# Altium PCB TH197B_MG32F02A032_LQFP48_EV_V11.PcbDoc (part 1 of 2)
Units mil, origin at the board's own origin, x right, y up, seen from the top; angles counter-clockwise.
Board outline 4094.49 x 2637.8 mil, 2 copper layers (Top Layer, Bottom Layer); 114 components, 111 nets, 502 pads, 245 vias.
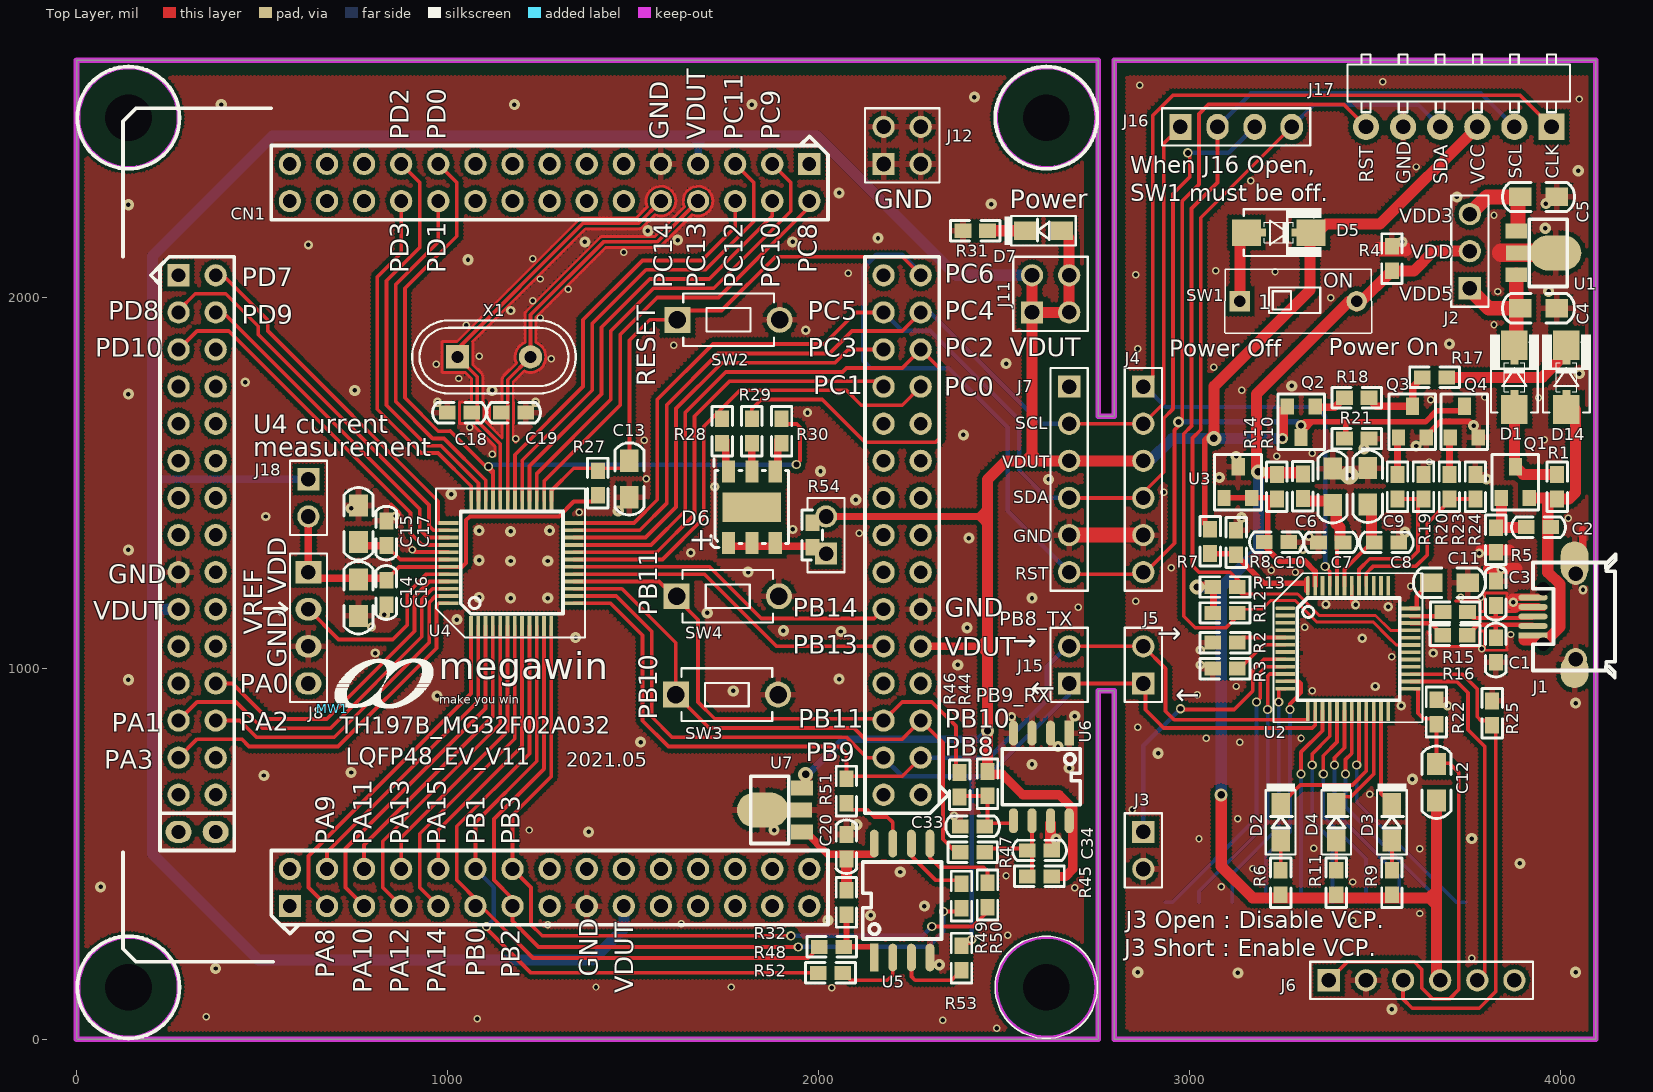
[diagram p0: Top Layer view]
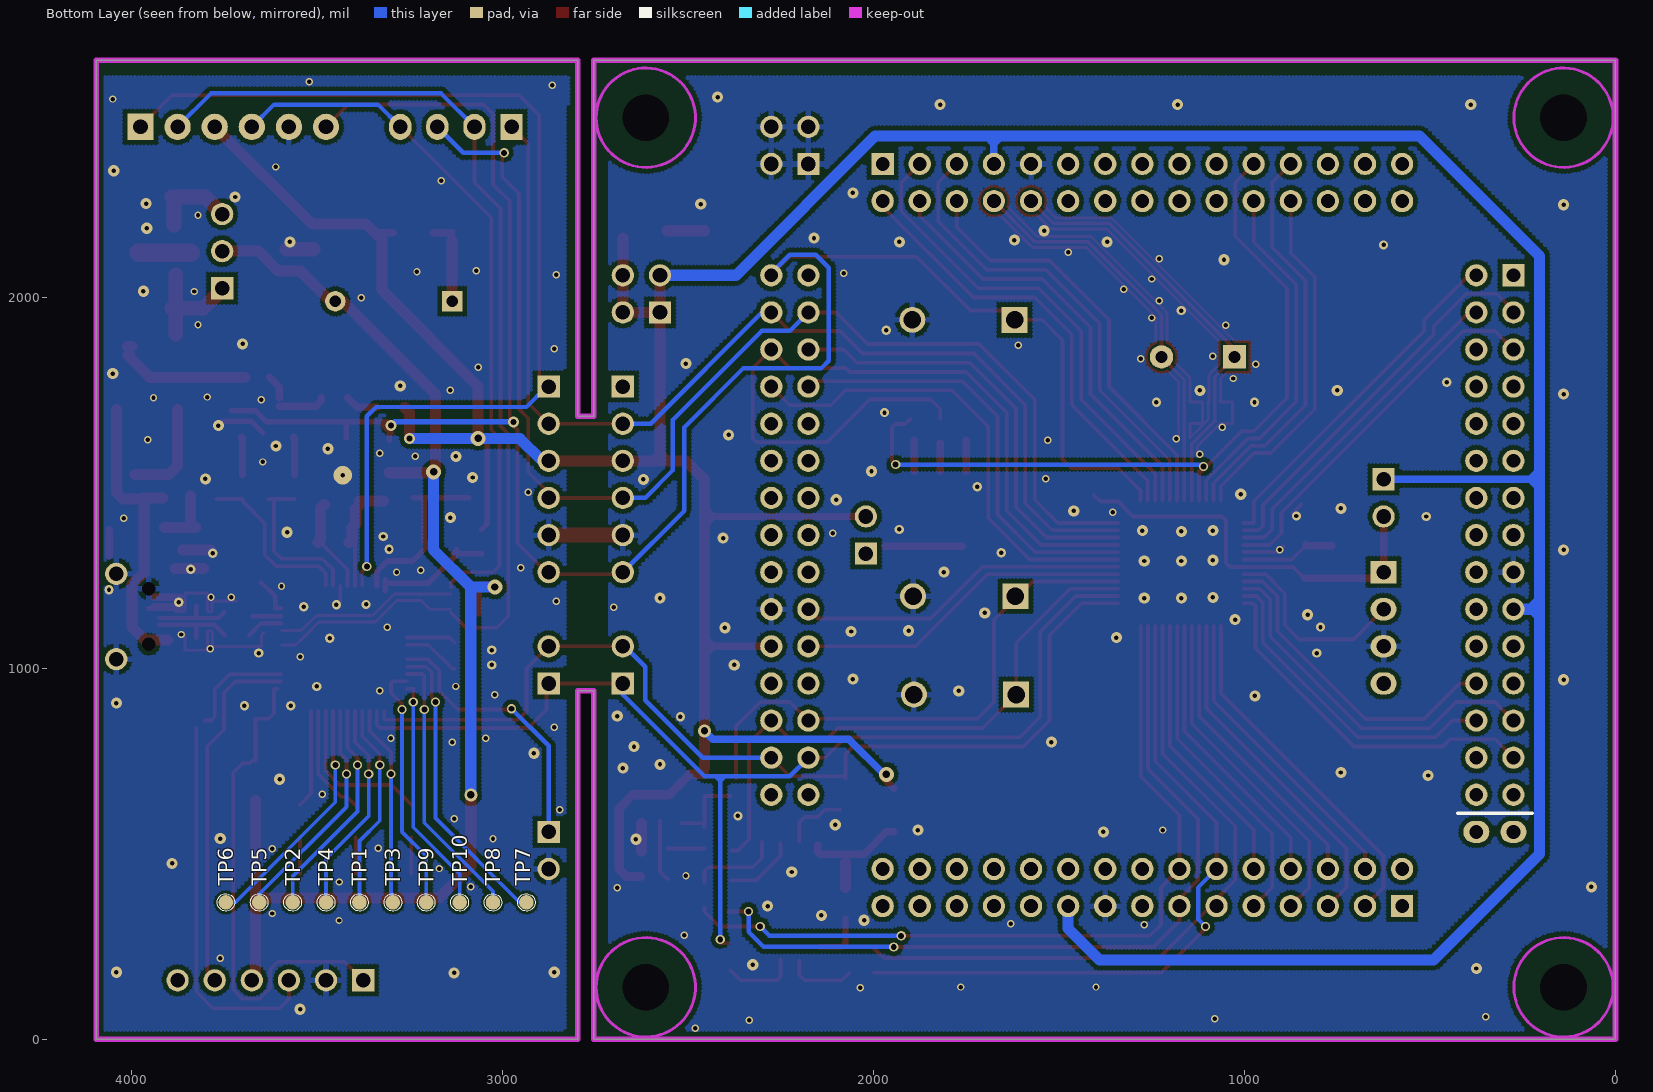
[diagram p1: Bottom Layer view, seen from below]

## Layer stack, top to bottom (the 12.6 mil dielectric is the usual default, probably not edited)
Top Layer: signal copper 1.4
Dielectric: dielectric 12.6, FR-4, Dk 4.8
Bottom Layer: signal copper 1.4

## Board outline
0,0 0,2637.8 2753.39,2637.8 2753.39,1678.74 2796.69,1678.74 2796.69,2637.8 4094.49,2637.8 4094.49,0 2796.69,0 2796.69,938.74 2753.39,938.74 2753.39,0

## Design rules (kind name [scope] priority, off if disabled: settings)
Clearance 12 [All] p1 off: gap=12
Clearance 7 [All] p2 off: gap=7
Clearance 6 [All] p3: gap=6
HoleSize 500-HoleSize [All] p1: absolutevalues=TRUE maxlimit=1500 minlimit=1 maxpercent=80.000 minpercent=20.000
PolygonConnect VIA [ISVIA] p1: connectstyle=Direct reliefconductorwidth=10 reliefentries=4 polygonreliefangle="90 Angle"
PolygonConnect "15 PolygonConnect" [All] p2: connectstyle=Relief reliefconductorwidth=15 reliefentries=4 polygonreliefangle="90 Angle"
RoomDefinition 2_MG32F02A032_V11 [InComponentClass('2_MG32F02A032_V11')] p1: confinementstyle=ConfineIn formatcopy=TRUE lockcomponents=FALSE outline -190,-175 4240.04,-175 4240.04,2710 -190,2710
RoomDefinition 1_MLink_V11 [InComponentClass('1_MLink_V11')] p2: confinementstyle=ConfineIn formatcopy=TRUE lockcomponents=FALSE outline -110,-220 4180,-220 4180,2775 -110,2775
RoutingVias [All] p1: holewidth=16 width=28 viastyle="Through Hole" minholewidth=16 minwidth=25 maxholewidth=28 maxwidth=50
ShortCircuit [All] p1 off: allowed=FALSE
SilkscreenOverComponentPads [All] p1: minsilkscreentomaskgap=10
SolderMaskExpansion [All] p1: expansion=4
UnRoutedNet [All] p1 off:
Width [All] p1: maxlimit=100 minlimit=6 preferedwidth=10
24 further rules are at their usual default settings.

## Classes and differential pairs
component class 1_MLink_V11: C1 C2 C3 C4 C5 C6 C7 C8 C9 C10 C11 C12 D1 D2 D3 D4 D5 D14 J1 J2 J3 J4 J5 J6 J16 J17 MW1 Q1 Q2 Q3 Q4 R1 R2 R3 R4 R5 R6 R7 R8 R9 R10 R11 R12 R13 R14 R15 R16 R17 R18 R19 R20 R21 R22 R23 R24 R25 SW1 TP1 TP2 TP3 TP4 TP5 TP6 TP7 TP8 TP9 TP10 U1 U2 U3
component class 2_MG32F02A032_V11: C13 C14 C15 C16 C17 C18 C19 C20 C33 C34 CN1 D6 D7 J7 J8 J11 J12 J15 J18 R27 R28 R29 R30 R31 R32 R44 R45 R46 R47 R48 R49 R50 R51 R52 R53 R54 SW2 SW3 SW4 U4 U5 U6 U7 X1

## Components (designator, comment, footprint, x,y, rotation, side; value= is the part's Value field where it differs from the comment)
C1 "15pF" 0603C 3825.04,1048.74 r90 top
C2 "0.1uF" 0603C 3940,1380 r0 top
C3 "15pF" 0603C 3825.04,1201.74 r270 top
C4 "4.7uF" 0805C 3940,1970 r0 top
C5 "4.7uF" 0805C 3940,2270 r0 top
C6 "4.7uF" 0805C 3385,1488.74 r90 top
C7 "0.1uF" 0603C 3380.04,1338.74 r180 top
C8 "0.1uF" 0603C 3530.04,1338.74 r0 top
C9 "4.7uF" 0805C 3480,1490 r90 top
C10 "0.1uF" 0603C 3234.09,1339.69 r180 top
C11 "4.7uF" 0805C 3700,1230 r0 top
C12 "4.7uF" 0805C 3665.04,692.74 r90 top
C13 "4.7uF" 0805C 1490,1510 r90 top
C14 "4.7uF" 0805C 760,1190 r270 top
C15 "4.7uF" 0805C 760,1389.21 r90 top
C16 "0.1uF" 0603C 834.94,1203.74 r90 top
C17 "0.1uF" 0603C 835,1363.74 r270 top
C18 "NC" 0603C 1032.04,1688.74 r0 top
C19 "NC" 0603C 1178.04,1688.74 r180 top
C20 "1uF" 0603C 2075.04,518.74 r270 top
C33 "47pF" 0603C 2415.04,573.74 r0 top
C34 "47pF" 0603C 2595.04,508.74 r180 top
CN1 "QFP122-CKT" QFP122-P2.54-CKT 1275.04,1358.74 r0 top locked
D1 "1N5817" DIODE_SMA_SOD323 3875,1783.74 r90 top
D2 "Yellow" 0805D 3245.04,585 r90 top
D3 "Green" 0805D 3545.04,585 r90 top
D4 "Red" 0805D 3395.04,585 r90 top
D5 "1N5817" DIODE_SMA_SOD323 3240,2173.74 r0 top
D6 "GTG5050RGBC" LED6P_RGB_SMD_50X50 1820.04,1433.74 r90 top
D7 "Yellow" 0805D 2605.83,2178.74 r180 top
D14 "1N5817" DIODE_SMA_SOD323 4015,1783.74 r90 top
J1 "Micro USB" JACK_USB_SMD290X220P065 3925.04,1139.21 r180 top (schematic designator J8)
J2 "2&3 (0 ohm)" PS3P254 3755.04,2023.74 r90 top
J3 "VCP Option" PS2P254 2875.04,558.74 r270 top
J4 "OnBoard ICP/SWD Connector" PS6P254 2875.04,1758.74 r270 top
J5 "NC" PS2P254 2875.04,958.74 r90 top
J6 "CON6" PS6P254 3375.04,158.74 r0 top
J7 "CON6" PS6P254 2675.04,1758.74 r270 top
J8 "1&2 (0 ohm)" PS4P254 625.04,1258.74 r270 top
J11 "CONN SOCKET 2x2/SM" PS2X2P254 2575.04,1958.74 r0 top
J12 "CONN SOCKET 2x2/SM" PS2X2P254 2175.04,2358.74 r0 top
J15 "NC" PS2P254 2675.04,958.74 r90 top
J16 "When J16 Open, SW1 must be off." PS4P254 2975.04,2458.74 r0 top
J17 "Off Board ICP/SWD Connector" PS6P254_90 3975.04,2458.74 r180 top locked
J18 "JUMPER" PS2P254 625.04,1508.74 r270 top
MW1 "MW-A4" MEGAWIN_3.4 690,890 r0 top
Q1 "IRLML6402" SOT23 3877.54,1500.71 r0 top
Q2 "2N3906" SOT23 3300.5,1663.74 r180 top
Q3 "3904" SOT23_132 3600.04,1663.74 r0 top
Q4 "3904" SOT23_132 3740.04,1663.74 r0 top
R1 "NC" 0603R#1 3990.04,1488.74 r270 top
R2 "0" 0603R#1 3095.04,1068.74 r0 top
R3 "NC" 0603R#1 3095.04,998.74 r0 top
R4 "3.3K" 0603R#1 3545.04,2103.74 r270 top
R5 "1M" 0603R#1 3825.04,1345.74 r270 top
R6 "1K" 0603R#1 3245.04,422 r270 top
R7 "30K" 0603R#1 3055.04,1341.74 r90 top
R8 "10K" 0603R#1 3125.04,1338.74 r270 top
R9 "1K" 0603R#1 3545.04,422 r270 top
R10 "10" 0603R#1 3305,1490 r90 top
R11 "1K" 0603R#1 3395.04,422 r270 top
R12 "1.5K" 0603R#1 3095.04,1148.74 r180 top
R13 "1.5K" 0603R#1 3095.04,1218.74 r180 top
R14 "1K" 0603R#1 3235,1488.74 r270 top
R15 "30" 0603R#1 3715.88,1151.05 r180 top
R16 "30" 0603R#1 3715.04,1088.74 r180 top
R17 "4.7K" 0603R#1 3660,1783.74 r0 top
R18 "1K" 0603R#1 3450.04,1728.74 r0 top
R19 "4.7K" 0603R#1 3560.04,1488.74 r270 top
R20 "10K" 0603R#1 3630.04,1488.74 r270 top
R21 "1M" 0603R#1 3450.04,1618.74 r180 top
R22 "47K" 0603R#1 3665.04,881.74 r90 top
R23 "4.7K" 0603R#1 3700.04,1488.74 r270 top
R24 "10K" 0603R#1 3770.04,1488.74 r270 top
R25 "47K" 0603R#1 3815.04,878.74 r270 top
R27 "47K" 0603R#1 1405.04,1498.74 r270 top
R28 "510" 0603R#1 1740.04,1638.74 r90 top
R29 "510" 0603R#1 1820.04,1638.74 r90 top
R30 "3K" 0603R#1 1900.04,1638.74 r90 top
R31 "1K" 0603R#1 2422.04,2178.74 r180 top
R32 "47K" 0603R#1 2075.04,368.74 r270 top
R44 "10K" 0603R#1 2455.04,688.74 r90 top
R45 "10K" 0603R#1 2595.04,438.74 r0 top
R46 "NC" 0603R#2 2380,685.74 r270 top
R47 "NC" 0603R#1 2415.04,503.74 r180 top
R48 "NC" 0603R#1 2035.04,248.74 r180 top
R49 "NC" 0603R#1 2385.04,385.74 r270 top
R50 "NC" 0603R#1 2455.04,388.74 r270 top
R51 "NC" 0603R#1 2075.04,668.74 r90 top
R52 "NC" 0603R#1 2032.04,178.74 r180 top
R53 "NC" 0603R#1 2385.04,218.74 r90 top
R54 "0" PS2p254+0603 2020,1308.74 r90 top
SW1 "SW KEY-SPST" DIP2_SW 3135.08,1988.74 r0 top
SW2 "SW TACT-SPST" SW_T_2P 1757.24,1938.74 r0 top
SW3 "SW TACT-SPST" SW_T_2P 1752.83,928.74 r0 top
SW4 "SW TACT-SPST" SW_T_2P 1755.04,1193.74 r0 top
TP1 "T POINT A" PIN1_1H0 3385.04,368.74 r90 bottom
TP2 "T POINT A" PIN1_1H0 3565.04,368.74 r90 bottom
TP3 "T POINT A" PIN1_1H0 3295.04,368.74 r180 bottom
TP4 "T POINT A" PIN1_1H0 3475.04,368.74 r180 bottom
TP5 "T POINT A" PIN1_1H0 3655.04,368.74 r180 bottom
TP6 "T POINT A" PIN1_1H0 3745.04,368.74 r180 bottom
TP7 "T POINT A" PIN1_1H0 2935.04,368.74 r180 bottom
TP8 "T POINT A" PIN1_1H0 3025.04,368.74 r180 bottom
TP9 "T POINT A" PIN1_1H0 3205.04,368.74 r180 bottom
TP10 "T POINT A" PIN1_1H0 3115.04,368.74 r90 bottom
U1 "AIC1734-33(SOT-89)" SOT89 3880,2119.06 r270 top
U2 "MG84FG516_LQFP48" LQFP48_7X7_050#1 3426.51,1053.13 r270 top locked
U3 "TL431A" SOT23 3130,1500.71 r0 top
U4 "MG32F02A_LQFP48" LQFP48_7X7_050#2 1171.3,1282.7 r0 top locked
U5 "MX25LXX-SOP" SO8_208P127 2225.04,373.74 r0 top
U6 "24C16-SOP" SO8_150P127 2675.04,824.96 r270 top
U7 "AIC1734-33(SOT-89)" SOT89 1955.04,617.8 r90 top
X1 "NC" X49U 1125.04,1838.74 r0 top

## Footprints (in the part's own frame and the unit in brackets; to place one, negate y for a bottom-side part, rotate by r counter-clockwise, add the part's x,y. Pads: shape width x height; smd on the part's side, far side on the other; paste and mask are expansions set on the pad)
0603C [mil]
  rect 45x38 smd: 1(33,0) 2(-33,0)
  silkscreen extent -72,-28 72,28
0603R#1 [mil]
  rect 45x38 smd: 1(33,0) 2(-33,0)
  silkscreen extent -67,-28 67,28
0603R#2 [mil]
  rect 45x38 smd: 1(-33,0) 2(33,0)
  silkscreen extent -67,-28 67,28
0805C [mil]
  rect 60x50 smd: 1(-49.21,0) 2(49.21,0)
  silkscreen extent -97,-39 97,39
0805D [mil]
  rect 60x50 smd: 1(-49.21,0) 2(49.21,0)
  silkscreen extent -87,-40 104,40
DIODE_SMA_SOD323 [mm]
  rect 2x1.8 smd: 1(-2.2,0) 2(2.2,0)
  rect 0.95x0.54 smd: 1(-1.35,0) 2(1.35,0)
  silkscreen extent -2.4,-1.68 2.92,1.68
DIP2_SW [mm]
  rect 1.4x1.4 hole 0.8: 1(0,0)
  round 1.4 hole 0.8: 2(8,0)
  silkscreen extent -1.02,-2.2 9.02,2.2
JACK_USB_SMD290X220P065 [mm]
  rect 1.9x1.8 on Mech2: 0(-2.85,-1.15) 0(-2.85,1.15)
  round 0.8 hole 0.9 unplated: 1(-0.7,1.9) 5(-0.7,-1.9)
  rect 2x0.4 smd: 1(0,1.3)
  oval 2x0.4 smd: 2(0,0.65) 3(0,0) 4(0,-0.65) 5(0,-1.3)
  round 1.524 hole 1: 5(-2.931,2.921) 6(-2.931,-2.921)
  oval 1.9x2.3 smd: 5(-2.85,3.75)
  oval 1.9x2.794 smd: 6(-2.85,-3.75)
  silkscreen extent -5.65,-4.25 -0.01,4.2
LED6P_RGB_SMD_50X50 [mm]
  rect 2x4 smd: 0(0,0)
  rect 1.5x0.9 smd: 1(-2.45,1.6) 2(2.45,1.6) 3(-2.45,0) 4(2.45,0) 5(-2.45,-1.6) 6(2.45,-1.6)
  silkscreen extent -2.76,-2.52 3.3,2.79
LQFP48_7X7_050#1 [mm]
  oval 0.254x1.35 smd: 1(-2.75,-4.292)
  rect 0.254x1.35 smd: 2(-2.25,-4.292) 3(-1.75,-4.292) 4(-1.25,-4.292) 5(-0.75,-4.292) 6(-0.25,-4.292) 7(0.25,-4.292) 8(0.75,-4.292) 9(1.25,-4.292) 10(1.75,-4.292) 11(2.25,-4.292) 12(2.75,-4.292) 25(2.763,4.292) 26(2.263,4.292) 27(1.763,4.292) 28(1.263,4.292) 29(0.763,4.292) 30(0.263,4.292) 31(-0.237,4.292) 32(-0.737,4.292) 33(-1.237,4.292) 34(-1.737,4.292) 35(-2.237,4.292) 36(-2.737,4.292)
  rect 1.35x0.254 smd: 13(4.286,-2.744) 14(4.286,-2.244) 15(4.286,-1.744) 16(4.286,-1.244) 17(4.286,-0.744) 18(4.286,-0.244) 19(4.286,0.256) 20(4.286,0.756) 21(4.286,1.256) 22(4.286,1.756) 23(4.286,2.256) 24(4.286,2.756) 37(-4.286,2.756) 38(-4.286,2.256) 39(-4.286,1.756) 40(-4.286,1.256) 41(-4.286,0.756) 42(-4.286,0.256) 43(-4.286,-0.244) 44(-4.286,-0.744) 45(-4.286,-1.244) 46(-4.286,-1.744) 47(-4.286,-2.244)
  oval 1.35x0.254 smd: 48(-4.286,-2.744)
  silkscreen extent -5.15,-5.09 5.05,5.11
LQFP48_7X7_050#2 [mm]
  rect 0.254x1.35 smd: 1(-2.75,-4.292) 2(-2.25,-4.292) 3(-1.75,-4.292) 4(-1.25,-4.292) 5(-0.75,-4.292) 6(-0.25,-4.292) 7(0.25,-4.292) 8(0.75,-4.292) 9(1.25,-4.292) 10(1.75,-4.292) 11(2.25,-4.292) 12(2.75,-4.292) 25(2.763,4.292) 26(2.263,4.292) 27(1.763,4.292) 28(1.263,4.292) 29(0.763,4.292) 30(0.263,4.292) 31(-0.237,4.292) 32(-0.737,4.292) 33(-1.237,4.292) 34(-1.737,4.292) 35(-2.237,4.292) 36(-2.737,4.292)
  rect 1.35x0.254 smd: 13(4.286,-2.744) 14(4.286,-2.244) 15(4.286,-1.744) 16(4.286,-1.244) 17(4.286,-0.744) 18(4.286,-0.244) 19(4.286,0.256) 20(4.286,0.756) 21(4.286,1.256) 22(4.286,1.756) 23(4.286,2.256) 24(4.286,2.756) 37(-4.286,2.756) 38(-4.286,2.256) 39(-4.286,1.756) 40(-4.286,1.256) 41(-4.286,0.756) 42(-4.286,0.256) 43(-4.286,-0.244) 44(-4.286,-0.744) 45(-4.286,-1.244) 46(-4.286,-1.744) 47(-4.286,-2.244) 48(-4.286,-2.744)
  silkscreen extent -5.15,-5.09 5.05,5.11
MEGAWIN_3.4 [mil]
  silkscreen extent 5,3 272,136
PIN1_1H0 [mm]
  round 1 smd: 1(0,0)
  silkscreen extent -0.6,-0.6 0.6,0.6
PS2P254 [mil]
  rect 60x60 hole 39.37: 1(0,0)
  round 60 hole 39.37: 2(100,0)
  silkscreen extent -50,-50 150,50
PS2p254+0603 [mil]
  rect 60x60 hole 39.37: 1(0,0)
  rect 45x38 smd: 1(17,36.85) 2(83,36.85)
  round 60 hole 39.37: 2(100,0)
  silkscreen extent -50,-50 150,64
PS2X2P254 [mil]
  rect 60x60 hole 39.37: 1(0,0)
  round 60 hole 39.37: 2(0,100) 3(100,0) 4(100,100)
  silkscreen extent -50,-50 150,150
PS3P254 [mil]
  rect 60x60 hole 39.37: 1(0,0)
  round 60 hole 39.37: 2(100,0) 3(200,0)
  silkscreen extent -50,-50 250,50
PS4P254 [mil]
  rect 60x70 hole 39.37: 1(0,0)
  oval 60x70 hole 39.37: 2(100,0) 3(200,0) 4(300,0)
  silkscreen extent -50,-50 350,50
PS6P254 [mil]
  rect 60x60 hole 39.37: 1(0,0)
  round 60 hole 39.37: 2(100,0) 3(200,0) 4(300,0) 5(400,0) 6(500,0)
  silkscreen extent -50,-50 550,50
PS6P254_90 [mm]
  rect 1.8x1.8 hole 1: 1(0,0)
  round 1.8 hole 1: 2(2.54,0) 3(5.08,0) 4(7.62,0) 5(10.16,0) 6(12.7,0)
  silkscreen extent -1.27,-4.95 13.97,-1
QFP122-P2.54-CKT [mil]
  rect 60x60 hole 37: 1(-700,-1000) 61(700,1000) 91(-1000,700)
  round 60 hole 37: 2(-700,-900) 3(-600,-1000) 4(-600,-900) 5(-500,-1000) 6(-500,-900) 7(-400,-1000) 8(-400,-900) 9(-300,-1000) 10(-300,-900) 11(-200,-1000) 12(-200,-900) 13(-100,-1000) 14(-100,-900) 15(0,-1000) 16(0,-900) 17(100,-1000) 18(100,-900) 19(200,-1000) 20(200,-900) 21(300,-1000) 22(300,-900) 23(400,-1000) 24(400,-900) 25(500,-1000) 26(500,-900) 27(600,-1000) 28(600,-900) 29(700,-1000) 30(700,-900) 31(1000,-700) 32(900,-700) 33(1000,-600) 34(900,-600) 35(1000,-500) 36(900,-500) 37(1000,-400) 38(900,-400) 39(1000,-300) 40(900,-300) 41(1000,-200) 42(900,-200) 43(1000,-100) 44(900,-100) 45(1000,0) 46(900,0) 47(1000,100) 48(900,100) 49(1000,200) 50(900,200) 51(1000,300) 52(900,300) 53(1000,400) 54(900,400) 55(1000,500) 56(900,500) 57(1000,600) 58(900,600) 59(1000,700) 60(900,700) 62(700,900) 63(600,1000) 64(600,900) 65(500,1000) 66(500,900) 67(400,1000) 68(400,900) 69(300,1000) 70(300,900) 71(200,1000) 72(200,900) 73(100,1000) 74(100,900) 75(0,1000) 76(0,900) 77(-100,1000) 78(-100,900) 79(-200,1000) 80(-200,900) 81(-300,1000) 82(-300,900) 83(-400,1000) 84(-400,900) 85(-500,1000) 86(-500,900) 87(-600,1000) 88(-600,900) 89(-700,1000) 90(-700,900) 92(-900,700) 93(-1000,600) 94(-900,600) 95(-1000,500) 96(-900,500) 97(-1000,400) 98(-900,400) 99(-1000,300) 100(-900,300) 101(-1000,200) 102(-900,200) 103(-1000,100) 104(-900,100) 105(-1000,0) 106(-900,0) 107(-1000,-100) 108(-900,-100) 109(-1000,-200) 110(-900,-200) 111(-1000,-300) 112(-900,-300) 113(-1000,-400) 114(-900,-400) 115(-1000,-500) 116(-900,-500) 117(-1000,-600) 118(-900,-600) 119(-1000,-700) 120(-900,-700)
  oval 70x60 hole 37: 121(-1000,-800) 122(-900,-800)
  silkscreen extent -1150,-1150 1075,1150
SO8_150P127 [mil]
  rect 67x25 smd: 1(0,0)
  oval 67x25 smd: 2(0,-50) 3(0,-100) 4(0,-150) 5(236.22,-150) 6(236.22,-100) 7(236.22,-50) 8(236.22,0)
  silkscreen extent 43,-180 193,30
SO8_208P127 [mm]
  rect 0.6x1.9 smd: 1(-1.905,-3.9)
  oval 0.6x1.9 smd: 2(-0.635,-3.9) 3(0.635,-3.9) 4(1.905,-3.9) 5(1.905,3.9) 6(0.635,3.9) 7(-0.635,3.9) 8(-1.905,3.9)
  silkscreen extent -2.69,-2.63 2.69,2.63
SOT23 [mil]
  rect 36x43.31 smd: 1(-37.5,-41.97) 2(37.5,-41.97)
  rect 36x46.06 smd: 3(0.5,41.97)
  silkscreen extent -63,-74 63,75
SOT23_132 [mil]
  rect 36x43.31 smd: 1(-37.5,-41.97) 3(37.5,-41.97)
  rect 36x46.06 smd: 2(0.5,41.97)
  silkscreen extent -63,-74 63,75
SOT89 [mm]
  rect 1.016x1.5 smd: 1(-1.5,0) 3(1.5,0)
  oval 2.4x3.5 smd: 2(0,2.7)
  rect 1.016x2.6 smd: 2(0,0.6)
  silkscreen extent -2.3,0.9 2.3,3.5
SW_T_2P [mil]
  rect 70x70 hole 47.24: 1(-137.79,0)
  round 70 hole 47.24: 2(137.8,0)
  silkscreen extent -122,-71 122,71
X49U [mm]
  rect 1.6x1.6 hole 0.8: 1(-2.5,0)
  round 1.6 hole 0.8: 2(2.5,0)
  silkscreen extent -5.6,-2.5 5.6,2.5

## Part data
C1 C3 C7 C12 C13 C14 C15 C16 C17: library part "CAP NP_Dup1"
C2 C8 C10: library part "CAP NP"
C4 C5: library part "C NP"
C6 C9 C11: library part CAP
C18 C19: library part "C NP_Dup1"
C20 C33 C34: library part CAP-NP
D1 D5 D14: library part "DIODE SCHOTTKY"
D2 D3 D4: library part Led0_0
D6: library part LED_GTG5050RGBC
D7: library part LED
J1 J7: library part CON6_Dup1
J2: library part CON3
J3 J5 J15: library part CON2
J4 J17: library part CON6
J8 J16: library part CON4
MW1: library part MW_A4_2
Q1: library part "MOSFET P GSD"
Q2: library part 2N3906_0
Q3 Q4: library part "NPN BCE"
R1 R2 R3 R4 R27: library part R_Dup4
R5 R6 R7 R8 R9 R11 R12 R13 R17 R18 R19 R22 R23 R25: library part R_Dup2
R10 R14 R15 R16 R28 R29 R30 R31 R32 R46 R47 R48 R49 R50 R51 R52 R53 R54: library part R_Dup5
R20 R21 R24: library part R_Dup1
R44 R45: library part R
U1 U7: library part AIC1722-33
U3: library part TL431/CYL
U4: library part IC-MG32F02A032-LQFP48
U5: library part ICM-25LXX
U6: library part ICM-24CXX
X1: library part CRYSTAL

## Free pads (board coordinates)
  round 120 hole 125.98 unplated: 0(140,140) 0(140,2483.43) 0(2613.39,140) 0(2613.39,2483.43)

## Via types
v1: diameter 30, hole 12, Top Layer to Bottom Layer, tented both sides, 93 vias
v2: diameter 20, hole 12, Top Layer to Bottom Layer, tented both sides, 89 vias
v3: diameter 25, hole 12, Top Layer to Bottom Layer, tented both sides, 32 vias
v4: diameter 25, hole 16, Top Layer to Bottom Layer, tented both sides, 21 vias
v5: diameter 40, hole 20, Top Layer to Bottom Layer, tented both sides, 4 vias
v6: diameter 30, hole 16, Top Layer to Bottom Layer, tented both sides, 3 vias
v7: diameter 35, hole 20, Top Layer to Bottom Layer, tented both sides, 2 vias
v8: diameter 50, hole 12, Top Layer to Bottom Layer, tented both sides, 1 vias

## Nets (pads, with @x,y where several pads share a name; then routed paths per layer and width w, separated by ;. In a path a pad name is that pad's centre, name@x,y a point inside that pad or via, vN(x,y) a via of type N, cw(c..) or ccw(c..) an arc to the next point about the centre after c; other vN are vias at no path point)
2.495V: C10.1 R14.1 U2.47 U3.1 U3.2 | length 478.9
  Top Layer w15: U3.1@3090,1458.74 U3.1@3092.5,1458.74 U3.2@3167.5,1458.74 3210,1458.74 3210,1455.74 C10.1@3210,1339.69 ; C10.1@3201.09,1339.69 3201.09,1328.91 3241.26,1288.74 3310.04,1288.74 3338.18,1260.6 U2.47@3338.18,1221.87 ; 3215,1458.74 3235,1458.74 R14.1@3240,1458.74
516P24: TP7.1 U2.9 | length 970.5
  Top Layer w10: v4(3180.04,908.74) 3190.04,918.74 3190.04,988.74 3205.22,1003.92 U2.9@3257.52,1003.92
  Bottom Layer w10: TP7.1@2935.04,368.74 2952.76,368.74 3180.04,596.02 ; 3066.4,482.38 3180.04,596.02 ; v4(3180.04,908.74) 3180.04,596.02
516P25: TP8.1 U2.10 | length 736.4
  Top Layer w10: v4(3210.04,888.74) 3210.04,978.74 3215.53,984.23 U2.10@3257.52,984.23
  Bottom Layer w10: TP8.1@3025.04,368.74 3025.04,398.59 3210.04,583.59 v4(3210.04,888.74)
516P26: TP9.1 U2.11 | length 674.3
  Top Layer w10: U2.11@3257.52,964.55 3294.23,964.55 3300.04,958.74 3300.04,933.74 3270.04,903.74 v4(3270.04,888.74)
  Bottom Layer w10: TP9.1@3205.04,368.74 3205.04,493.74 3270.04,558.74 v4(3270.04,888.74)
516P27: TP10.1 U2.12 | length 649.5
  Top Layer w10: v4(3240.04,908.74) 3240.04,941.97 3237.15,944.86 U2.12@3257.52,944.86
  Bottom Layer w10: TP10.1@3115.04,368.74 3115.04,446.17 3240.04,571.17 v4(3240.04,908.74)
516P32: TP3.1 U2.15 | length 762.5
  Top Layer w10: v4@3300.04,713.74 v4(3300.04,715) 3300.04,773.74 3357.86,831.56 U2.15@3357.86,884.39
  Bottom Layer w10: TP3.1@3300.04,373.74 3300.04,628.74 ; 3300.04,400.87 3300.04,628.74 ; v4@3300.04,713.74 3300.04,628.74
516P33: TP1.1 U2.16 | length 558.1
  Top Layer w10: v4(3330.04,738.74) 3330.04,768.74 3377.55,816.25 U2.16@3377.55,884.39
  Bottom Layer w10: v4(3330.04,738.74) 3330.04,588.89 3385.04,533.89 TP1.1@3385.04,368.74
516P34: TP4.1 U2.17 | length 578.7
  Top Layer w10: v4@3360.04,713.74 v4(3360.04,715) 3360.04,763.74 3397.23,800.93 U2.17@3397.23,884.39
  Bottom Layer w10: v4@3360.04,713.74 3360.04,601.31 3475.04,486.31 TP4.1@3475.04,368.74
516P35: TP2.1 U2.18 | length 599.3
  Top Layer w10: v4(3390.04,738.74) 3390.04,758.74 3416.92,785.62 U2.18@3416.92,884.39
  Bottom Layer w10: v4(3390.04,738.74) 3390.04,613.74 3565.04,438.74 TP2.1@3565.04,368.74
516P36: TP5.1 U2.19 | length 619.9
  Top Layer w10: v4@3420.04,713.74 v4(3420.04,715) 3420.04,753.74 3436.6,770.3 U2.19@3436.6,884.39
  Bottom Layer w10: v4@3420.04,713.74 3420.04,626.17 3655.04,391.17 TP5.1@3655.04,368.74
516P37: TP6.1 U2.20 | length 655.2
  Top Layer w10: v4(3450.04,738.74) 3456.29,744.99 U2.20@3456.29,884.39
  Bottom Layer w10: v4(3450.04,738.74) 3450.04,638.59 3719.89,368.74 TP6.1@3745.04,368.74
CHIP_VDD: C14.1 C16.1 J8.1 J18.2 R27.1 U4.43 | length 1144.1
  Top Layer w10: C16.1@835.04,1238.74 838.04,1241.74 C16.1@841.54,1245.24 ; 935.81,1273.11 U4.43@1002.56,1273.11
  Top Layer w11: C16.1@841.54,1245.24 869.41,1273.11 U4.43@1002.56,1273.11 1039.41,1273.11 1050.04,1283.74 1050.04,1398.74 1060.04,1408.74 1300.04,1408.74 1340.04,1448.74 1388.04,1448.74 R27.1@1405.04,1465.74
  Top Layer w20: J8.1@625.04,1258.74 J18.2@625.04,1408.74 ; J8.1@642.04,1241.74 760,1241.74 834.94,1241.74 C16.1@838.04,1241.74
D+: C3.1 J1.3 R15.2 | length 211.2
  Top Layer w12: R15.2@3748.88,1151.05 3764.71,1135.21 J1.3@3925.04,1135.21 ; 3825.04,1140.21 C3.1@3825.04,1168.74
D-: C1.1 J1.2 R16.2 | length 219.3
  Top Layer w12: R16.2@3748.04,1088.74 3776.51,1117.21 J1.2@3925.04,1117.21 ; C1.1@3825.04,1081.74 3825.04,1112.21
DET_VDUT: R7.2 R8.1 U2.48 | length 338.6
  Top Layer w15: R7.2@3055.04,1308.74 3125.04,1308.74 R8.1@3132.6,1308.74 ; R8.1@3122.6,1318.74 R8.1@3130.32,1311.02 ; R8.1@3122.8,1305.98 3124.04,1304.74 3200.04,1228.74 3310.98,1228.74 ; U2.48@3315.04,1208.74 3315.04,1221.87 U2.48@3315.04,1238.74
DUT_CLK: J4.1 J17.1 U2.45 | length 2858.5
  Top Layer w10: J4.1@2875.04,1758.74 2900.04,1783.74 2900.04,2488.74 2955.04,2543.74 3890.04,2543.74 J17.1@3975.04,2458.74 ; v4(3364.92,1273.74) 3377.55,1261.11 U2.45@3377.55,1221.87
  Bottom Layer w12: J4.1@2875.04,1758.74 2880.04,1758.74 2935.04,1703.74 3339.92,1703.74 3364.92,1678.74 v4(3364.92,1273.74)
DUT_RST: C13.2 CN1.59 J4.6 J7.6 J17.6 Q2.3 Q4.2 R21.1 R27.2 SW2.1 U4.25 | length 5757
  Top Layer w10: U4.25@1280.07,1451.69 1280.07,1478.77 1340.04,1538.74 1405.04,1538.74 1465.83,1538.74 1488.15,1561.06 1490.04,1562.95 1490.04,1883.74 1545.04,1938.74 SW2.1@1619.45,1938.74 ; SW2.1@1630.95,1963.74 1738.54,1963.74 1883.54,2108.74 2225.04,2108.74 CN1.59@2275.04,2058.74 ; J7.6@2676.04,1252.74 2875.04,1252.74 2878.04,1255.74 2958.79,1336.49 2958.79,1641.49 2975.54,1658.24 2980.04,1662.74 2980.04,1663.74 2980.04,2258.74 3025.04,2303.74 3025.04,2493.74 3050.04,2518.74 3415.04,2518.74 J17.6@3475.04,2458.74
  Top Layer w15: Q2.3@3300,1633.74 Q2.3@3305,1638.74 ; v6(3300,1653.74) 3310,1663.74 3330,1663.74 ; Q2.3@3305,1613.74 3305,1621.77 Q2.3@3305,1638.74 ; v6@3305,1656.74 3305,1653.74 Q2.3@3305,1638.74 ; R21.1@3420,1620.74 3420,1663.74 ; Q4.2@3730.63,1693.74 3665,1693.74 3635,1663.74 3420,1663.74 ; Q2.3@3305,1638.74 3310,1643.74 3330,1663.74 ; 3330,1663.74 3420,1663.74
  Bottom Layer w12: CN1.59@2275.04,2058.74 CN1.59@2280.04,2058.74 ; CN1.59@2295.04,2058.74 CN1.59@2280.04,2058.74 ; J7.6@2675.04,1258.74 2510.04,1423.74 2510.04,1648.74 2350.04,1808.74 2140.04,1808.74 2120.04,1828.74 2120.04,2078.74 2155.04,2113.74 2225.04,2113.74 2277.54,2061.24 CN1.59@2280.04,2058.74
  Bottom Layer w15: v6(2970.04,1663.74) 3290,1663.74 v6(3300,1653.74)
FAIL: D4.2 U2.22 | length 305.7
  Top Layer w10: D4.2@3395.04,629.74 3397.28,631.98 3419.04,653.74 3435.04,653.74 3495.66,714.36 U2.22@3495.66,884.39
FLASH_CEN: R32.1 R48.2 U5.1 | length 141.1
  Top Layer w15: R32.1@2075.04,325.74 2075.04,258.74 2076.54,257.24 2085.04,248.74 U5.1@2145.04,248.74
FLASH_D0: R50.2 U5.5 | length 245
  Top Layer w10: U5.5@2300.04,532.28 U5.5@2300.04,527.28 2300.04,488.74 2325.04,463.74 2445.04,463.74 2455.04,453.74 R50.2@2455.04,421.74
FLASH_D1: R52.2 U5.2 | length 188
  Top Layer w10: R52.2@2065.04,178.74 2085.04,158.74 2185.04,158.74 2200.04,173.74 U5.2@2200.04,212.2
FLASH_D2: R53.2 U5.3 | length 196.8
  Top Layer w10: U5.3@2250.04,215.2 2250.04,168.74 2260.04,158.74 2358.04,158.74 R53.2@2385.04,185.74
FLASH_D3: R51.2 U5.7 | length 176
  Top Layer w10: R51.2@2090.04,618.74 2130.04,618.74 2150.04,598.74 2185.04,598.74 2200.04,583.74 U5.7@2200.04,532.28
FLASH_SCK: R49.2 U5.6 | length 195.5
  Top Layer w10: U5.6@2250.04,527.28 2250.04,493.74 2315.04,428.74 R49.2@2385.04,428.74
GND_POWER: C1.2 C3.2 C4.2 C5.2 C6.2 C7.1 C8.1 C9.2 C10.2 C11.2 C13.1 C14.2 C15.2 C16.2 C17.2 C18.2 C19.2 C20.2 C33.2 C34.2 CN1.17 CN1.41 CN1.69 CN1.107 J1.4 J1.5 J1.6 J3.2 J4.5 J6.2 J7.5 J8.3 J12.1 J12.2 J12.3 J12.4 J17.5 Q3.3 Q4.3 R2.2 R3.2 R4.2 R5.1 R8.2 R20.2 R21.2 R22.1 R24.2 R25.2 R31.1 SW2.2 SW3.2 SW4.2 U1.2 U2.42 U3.3 U4.41 U5.4 U6.1 U6.2 U6.3 U6.4 U6.7 U7.2 | length 6567.9
  Top Layer w8: 1067.75,1880.24 1160.6,1973.08 1243.1,2055.58 1371.25,2183.74 1515.04,2183.74 ; 1068.11,1880.24 1068.11,1818.46 1090.64,1795.93 cw(c1080.04,1785.32) 1095.04,1785.32 ; 1069.44,1655.57 1127.27,1597.74 1127.27,1576.53 v2@1127.27,1571.74 ; 1090.65,1795.92 cw(c1080.04,1785.32) 1095.04,1785.32 ; 1095.04,1717.74 1095.04,1785.32 ; 1097.54,1717.74 1097.54,1669.89 1146.96,1620.48 1146.96,1659.74 1112.54,1659.74 1112.54,1717.74 1146.96,1717.74 1146.96,1777.23 ; 1176.96,1659.74 1176.96,1618.74 1176.96,1615.77 1178.97,1613.76 v2@1183.96,1608.77 ; 1176.96,1717.74 1176.96,1771.02 1206.71,1800.78 ccw(c1223.46,1838.74) 1264.96,1838.74 ccw(c1223.46,1838.74) 1238.46,1877.43 1238.46,1943.74 1238.46,1945.95 ; 1177.54,1659.74 1177.54,1717.74 ; 1212.85,1962.77 ccw(c1223.46,1952.17) 1208.46,1952.17 ; 3642.54,1095.71 3648.54,1089.71 3648.54,1058.74 3714.54,1058.74 ; 3715.54,1058.74 3781.54,1058.74 3781.54,1098.2 ; 3716.38,1181.05 3730,1181.05 3782.38,1181.05 3782.38,1152.21 3795.04,1152.21 3795.04,1190.64 3795.04,1202.24 3855.04,1202.24 3855.04,1152.21 3879.86,1152.21 cw(c3893.54,1139.21) 3893.54,1158.09 3925.04,1158.09 J1.4@3956.54,1158.09 ; 3783.55,1100.21 3795.04,1100.21 3795.04,1052.74 3795.04,1048.24 3855.04,1048.24 3855.04,1088.21 v2@3861.04,1094.21 ; J1.4@3925.04,1163.09 J1.4@3956.54,1163.09 ; 1025.32,1880.24 1059.38,1914.3 ; 1025.32,1880.24 1059.38,1914.3 ; 1025.32,1880.24 985.12,1880.24 985.12,1797.24 1046.9,1797.24 1065.04,1779.1 1065.04,1717.74 1032.54,1717.74 1032.54,1659.74 1059.94,1659.74 1066.49,1659.74 ; 1059.38,1914.3 1239.38,2094.3 1354.43,2209.34 ; 1066.49,1659.74 ccw(c1080.04,1666.18) 1069.43,1655.57 cw(c1080.04,1666.18) 1066.49,1659.74 ; 1146.96,1777.23 cw(c1161.96,1777.23) 1151.34,1787.83 ; 1146.96,1777.23 cw(c1161.96,1777.23) 1151.35,1787.84 ; 1151.36,1787.84 1185.5,1821.99 cw(c1223.46,1838.74) 1208.46,1877.43 1208.46,1952.17 ; 1208.46,1952.17 cw(c1223.46,1952.17) 1212.86,1962.77 1235.38,1985.3 1409.43,2159.34 ; 1238.46,1945.95 v2@1243.1,1950.58 ; 1238.46,1945.95 v2@1243.1,1950.58 ; v2@1243.1,1950.58 1319.1,2026.59 1426.25,2133.74 1475.04,2133.74 1565.04,2133.74 ; 1354.44,2209.35 cw(c1365.04,2198.74) 1365.04,2213.74 ; 1354.43,2209.35 cw(c1365.04,2198.74) 1365.04,2213.74 ; 1365.04,2213.74 1508.83,2213.74 1538.21,2243.13 cw(c1575.04,2258.74) 1615.04,2258.74 cw(c1575.04,2258.74) 1559.43,2221.91 1528.1,2190.58 1525.65,2188.14 ; 1409.44,2159.35 cw(c1420.04,2148.74) 1420.04,2163.74 ; 1409.43,2159.35 cw(c1420.04,2148.74) 1420.04,2163.74 ; 1420.04,2163.74 1539.94,2163.74 1558.83,2163.74 1638.21,2243.13 cw(c1675.04,2258.74) 1715.04,2258.74 cw(c1675.04,2258.74) 1659.43,2221.91 1575.65,2138.14 ; 1515.04,2183.74 ccw(c1515.04,2198.74) 1525.65,2188.13 ; 1515.04,2183.74 ccw(c1515.04,2198.74) 1525.64,2188.13 ; 1565.04,2133.74 ccw(c1565.04,2148.74) 1575.64,2138.13 ; 1565.04,2133.74 ccw(c1565.04,2148.74) 1575.65,2138.13
  Top Layer w10: 3436.6,1177.75 U2.42@3436.6,1221.87
  Top Layer w11: 847.02,1440.64 868.8,1418.86 871,1416.67 ; 895.04,1328.74 v2(905.04,1318.74) 911.3,1312.48 U4.41@1002.56,1312.48
  Top Layer w15: Q3.3@3645.29,1634.03 3676.24,1664.98 3753.7,1664.98 v1(3764.94,1653.74)
  Top Layer w20: v3@3868.92,1166.05 3872.21,1166.05 3925.04,1166.05 J1.4@3940.04,1166.05 ; 3868.92,1191.64 3872.21,1191.64 3925.04,1191.64 J1.5@3940.04,1191.64 ; J1.6@4058.69,1302.62 4058.69,1373.74
  Top Layer w30: C34.2@2625.04,506.84 2625.04,508.74 2625.04,538.74 U6.7@2625.04,580.64 ; v3@3785.04,1318.74 3825.04,1318.74 3862.04,1318.74 ; 3805.04,1268.74 3825.04,1268.74 3839.94,1268.74 3882.04,1268.74
  Top Layer w40: J7.5@2675.04,1358.74 J4.5@2875.04,1358.74 ; 3509.94,2128.74 3545.04,2128.74 3572.6,2128.74 3581.04,2128.74
  Top Layer w50: 3840,2119.06 U1.2@3903.62,2119.06 U1.2@3980,2119.06
  other v1: 3545.04,80.64 3129.94,178.74 2860.04,180.64 4040.04,180.64 375.04,190.64 2325.04,200.64 2025.04,320.64 2139.94,333.74 2285.04,358.74 65,410.64 2220.04,450.64 3889.94,473.74 2639.94,538.74 3760,540.64 1379.94,558.74 1879.94,563.74 2102.73,577.9 3600.04,700.64 505.04,710.64 739.94,718.74 2675.04,730.64 2575.04,740.64 2915.04,770.64 2645.04,788.74 1520,800.64 2690.04,870.64 4040.04,905.64 972,925.29 1769.94,938.74 139.94,968.74 2055.04,970.64 2375.04,1008.74 1345.04,1082.22 2059.94,1098.74 1905.04,1100.64 2399.94,1108.74 1025.04,1130.64 829.94,1143.74 1699.94,1148.74 1169.94,1188.74 1269.94,1188.74 2575.04,1188.74 1085.04,1190.64 1809.94,1258.74 1169.94,1288.74 1269.94,1288.74 1085.04,1290.64 139.94,1318.74 2405.04,1350.64 3580,1366.3 1169.94,1368.74 1085.04,1370.64 1275.04,1370.64 3140,1405.67 1460.04,1423.74 740,1430.64 2099.94,1453.74 1009.94,1468.74 2619.94,1508.74 3800,1510 3079.94,1513.74 2005.04,1530.64 3125.04,1570.64 3470,1591.18 3609.94,1598.74 2389.94,1628.74 139.94,1738.74 749.94,1748.74 1119.94,1748.74 3275,1760.64 4049.94,1793.74 2505.04,1820.64 3700,1873.74 3967.04,2015.64 1055.04,2100.64 1369.94,2148.74 1929.94,2148.74 3572.6,2148.74 1619.94,2153.74 2159.94,2158.74 1539.94,2178.74 3958.04,2185.64 139.94,2248.74 2465.04,2250.64 3959.94,2251.74 3719.94,2269.74 2055.04,2280.64 4047.04,2340.64 389.94,2518.74 1179.94,2518.74 1819.94,2518.74 2419.94,2538.74
  other v2: 2479.94,30 2335,50.64 1079.94,55 349.94,60 2035,138.74 1400,140.64 1765,140.64 3759.94,218.74 2509.94,280 1270.04,308.74 1630.04,310.64 3440,320 3619.94,338.74 2689.94,408.74 3085,410.64 3439.94,423.74 2505,440.64 3169.49,460 3619.94,513.74 3334.49,515 3025,540.64 1219.94,563.74 3129.94,593.74 2845.04,618.74 3485.04,660.64 3135.04,800.64 3045,810.64 3300.04,810.64 2860.04,840.64 3019.94,928.74 3329.94,938.74 3125,950.64 3545.04,1030.64 3787.54,1052.74 3865,1090.64 3310.04,1110.64 2699.94,1163.74 2855.04,1180.64 3730,1190.58 3785,1190.64 3595.04,1220.64 3285.04,1258.74 3219.94,1263.74 2950.04,1270.64 2109.94,1363.74 4019.94,1403.74 1355.04,1420.64 2929.94,1473.74 1535.04,1510.64 3645,1555.67 3235,1570.64 1119.94,1576.53 3329.94,1578.71 1529.94,1613.74 3955,1615 1183.96,1618.74 1059.94,1648.74 3649.94,1723.74 3939.94,1728.74 3795,1730.64 3139.94,1748.74 1030.04,1780.64 3065.04,1810.64 969.94,1818.74 1279.94,1833.74 1085.04,1840.64 2860,1860.64 1610.04,1870.64 1049.94,1923.74 3820,1925 1249.94,1943.74 1230.04,1990.64 3379.94,1998.74 3829.94,2015 1325.04,2020.64 1249.94,2048.74 2855,2060.64 2079.94,2063.74 3229.94,2068.74 3070.04,2070.64 1229.94,2103.74 1475.04,2120.64 3820,2220.64 3165.04,2313.74 3610.04,2350.64 4049.94,2533.74 2865,2570.64 3520,2580.64
  other v3: 2365.04,601.74 2519.94,868.74 3569.94,898.74 3695.04,898.74 3500,950.64 3028.11,1008.74 805.04,1040.64 3656.04,1040.64 3028.11,1048.74 3465.04,1080.64 795.04,1110.64 3535.04,1165.74 3447.04,1170.74 3367.04,1171.74 3872.21,1177.6 4059.94,1211.45 3839.94,1266.74 3780,1310 1655.04,1310.64 3305.04,1320.64 3321.04,1354.74 1929.94,1373.74 509.94,1408.74 859.94,1410 1719.94,1488.74 1969.94,1688.74 972.88,1716.3 1237.2,1716.3 455.04,1770.64 1965,1910.64 1169.94,1963.74 625.04,2140.64
  other v8: 3430,1520
I2C_SCL: C34.1 R45.2 R47.2 U6.6 | length 265.3
  Top Layer w10: R47.2@2455.04,513.74 C34.1@2555.04,513.74 ; R45.2@2555.04,431.74 R45.2@2562.04,438.74 2575.04,451.74 2575.04,508.74 U6.6@2575.04,588.74
I2C_SDA: C33.1 R44.2 R46.2 U6.5 | length 217
  Top Layer w10: R46.2@2385.04,655.74 R44.2@2455.04,655.74 C33.1@2455.04,581.74 ; C33.1@2455.04,571.74 2455.04,573.74 C33.1@2455.04,581.74 ; U6.5@2518.04,581.74 C33.1@2455.04,581.74
ICP/SWD_SCL: J16.2 J17.2 R12.2 U2.31 | length 2955.1
  Top Layer w8: R12.2@3140.04,1158.74 3195.04,1158.74 3219.04,1182.74 3284,1182.74 3342,1124.74 3494,1124.74 3533.9,1084.84 ; 3533.94,1084.84 3556.31,1062.47 U2.31@3595.5,1062.47
  Top Layer w10: J16.2@3075.04,2483.74 J16.2@3075.04,2458.74 3075.04,2308.74 3005.04,2238.74 3005.04,1652.74 2983.79,1631.49 2983.79,1139.99 3015.04,1108.74 3098.04,1108.74 3133.04,1143.74 R12.2@3138.04,1148.74
  Bottom Layer w12: J16.2@3075.04,2458.74 3165.04,2548.74 3785.04,2548.74 J17.2@3875.04,2458.74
